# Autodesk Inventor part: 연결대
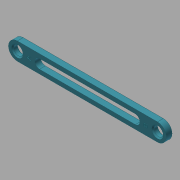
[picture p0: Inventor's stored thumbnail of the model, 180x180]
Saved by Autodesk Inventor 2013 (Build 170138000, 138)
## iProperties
Created: 2017-07
Part Number: 연결대
Material: 스테인리스강
Document SubType Name: Modeling
Designer: mduedu
Density: 8.08 g/cm^3
Mass: 46.85 g
Surface Area: 49.3916 cm^2
Volume: 5.79827 cm^3
Author: mduedu
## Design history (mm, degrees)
sketch "스케치1"
  geometry: L1 (-67.5, 0)-(67.5, 0); L2 (-67.5, -7.5)-(67.5, -7.5); L3 (67.5, -7.5)-(67.5, 7.5); L4 (67.5, 7.5)-(-67.5, 7.5); L5 (-67.5, 7.5)-(-67.5, -7.5); L6 (-67.5, -7.5)-(67.5, 7.5); L7 (67.5, -7.5)-(-67.5, 7.5); 2 further points
  constraints: 14 end point, 4 midpoint, 2 horizontal, 2 parallel, 1 coincident, 1 perpendicular
  dimensions: "d0" = 135 distance of L1.start L1.end; "d2" = 15 distance of L2.end L3.end
extrude "돌출1" new body sketch "스케치1" distance "d3" = 5; taper "d4" = 0 deg
fillet "모깎기1"
fillet "모깎기2"
sketch "스케치2"
  geometry: C1 r 4 at (60, 0); A1 r 7.5 centre (60, 0) between (60, -7.5) and (60, 7.5) reference; 1 further point
  constraints: 1 centre point, 1 coincident
  dimensions: "d5" = 8 diameter of C1
extrude "돌출2" cut sketch "스케치2" stored distance "d6" = 10; taper "d7" = 0 deg
chamfer "모따기1" distance "d8" = 1; stored, may be unused: second distance "d9" = 2, angle "d10" = 45 deg
sketch "스케치3"
  geometry: L1 (-45, 0)-(45, 0); L2 (-45, -4)-(45, -4); L3 (45, -4)-(45, 4); L4 (45, 4)-(-45, 4); L5 (-45, 4)-(-45, -4); L6 (-45, -4)-(45, 4); L7 (45, -4)-(-45, 4); 2 further points
  constraints: 14 end point, 4 midpoint, 2 horizontal, 2 parallel, 1 coincident, 1 perpendicular
  dimensions: "d11" = 90 distance of L1.start L1.end; "d13" = 8 distance of L2.end L3.end
extrude "돌출3" cut sketch "스케치3" stored distance "d14" = 10; taper "d15" = 0 deg
fillet "모깎기3"
fillet "모깎기4"
sketch "스케치4"
  geometry: L1 (-60, 0)-(60, 0); C1 r 5 at (-60, 0) reference; C2 r 5 at (60, 0) reference; 3 further points
  constraints: 2 end point, 2 point on line, 1 horizontal, 2 other
  dimensions: "d16" = 50 distance of point (-50, 0) point (0, 0); "d17" = 50 distance of point (50, 0) point (0, 0)
feature "엠보싱1" sketch "스케치4" dims "d0" = 135, "d2" = 15, "d18" = 0.5, "d19" = 0
node "솔리드1"
mirror "대칭1"
